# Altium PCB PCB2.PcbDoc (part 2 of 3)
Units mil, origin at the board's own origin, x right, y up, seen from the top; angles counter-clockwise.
Board outline 10275.59 x 4173.23 mil, 2 copper layers (Top Layer, Bottom Layer); 158 components, 159 nets, 776 pads, 338 vias.
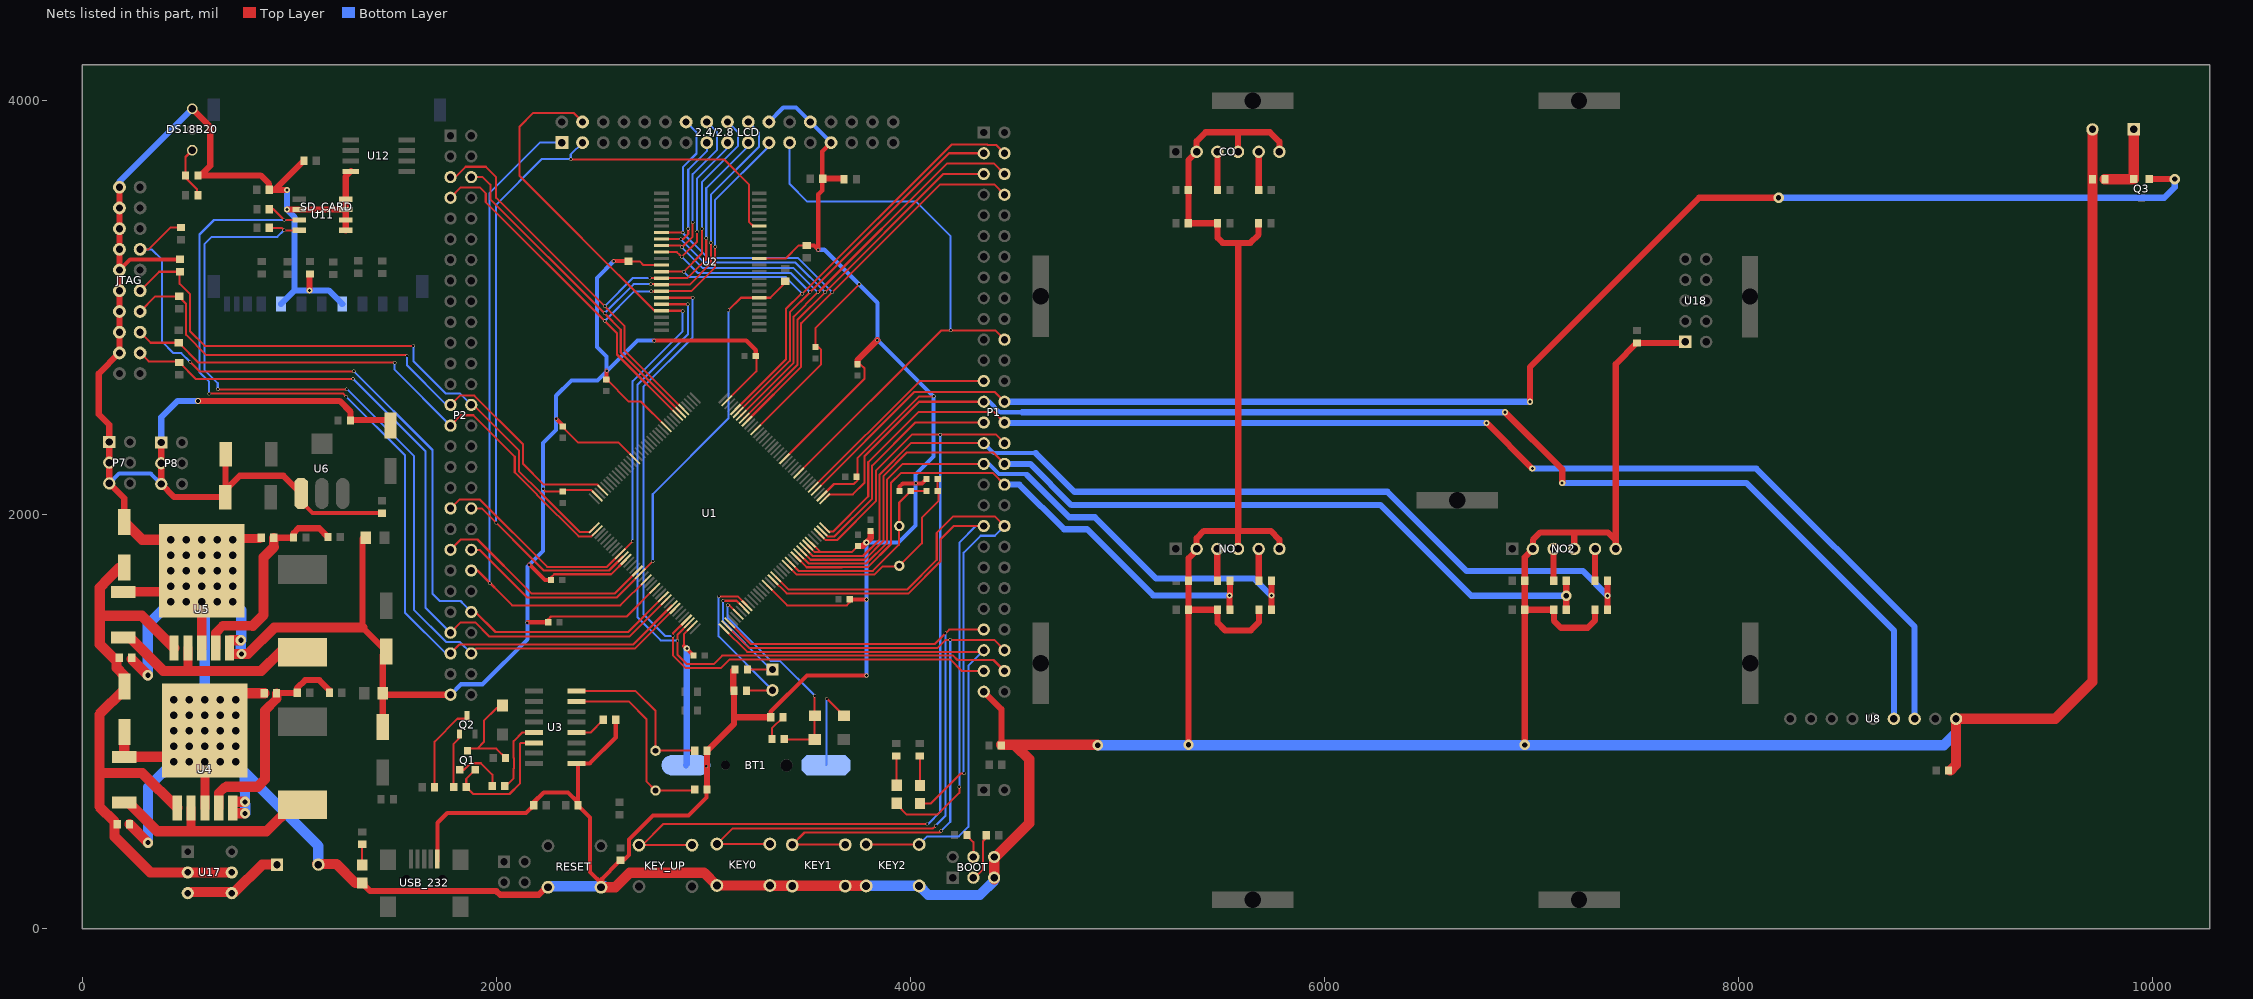
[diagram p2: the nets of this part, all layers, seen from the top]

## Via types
v1: diameter 16, hole 12, Top Layer to Bottom Layer, 183 vias
v2: diameter 60, hole 36, Top Layer to Bottom Layer, 50 vias
v3: diameter 27.56, hole 27.56, Top Layer to Bottom Layer, 32 vias
v4: diameter 30, hole 15, Top Layer to Bottom Layer, 27 vias
v5: diameter 50, hole 25, Top Layer to Bottom Layer, 19 vias
v6: diameter 125.98, hole 125.98, Top Layer to Bottom Layer, 16 vias
v7: diameter 20, hole 15, Top Layer to Bottom Layer, 4 vias
v8: diameter 196.85, hole 118.11, Top Layer to Bottom Layer, 4 vias
v9: diameter 30, hole 20, Top Layer to Bottom Layer, 1 vias
v10: diameter 40, hole 20, Top Layer to Bottom Layer, 1 vias
v11: diameter 50, hole 28, Top Layer to Bottom Layer, 1 vias

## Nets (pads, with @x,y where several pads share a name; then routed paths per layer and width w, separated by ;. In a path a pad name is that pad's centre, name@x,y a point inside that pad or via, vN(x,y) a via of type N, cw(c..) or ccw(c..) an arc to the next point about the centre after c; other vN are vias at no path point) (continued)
FSMC_D8: "2.4/2.8 LCD.14" P1.8 U1.64 U2.29 | length 3389.4
  Top Layer w10: U2.29@2797.28,3362.02 v1(2901.37,3362.02) ; U1.64@3210.96,2451.54 3472.37,2712.95 3472.37,2923.61 ; 3473.37,2923.61 v1(3622.37,3072.61) 4144.37,3594.61 4404.37,3594.61 P1.8@4454.37,3544.61
  Bottom Layer w10: v1@2898.87,3362.11 3021.37,3239.61 3455.37,3239.61 v1(3622.37,3072.61) ; v1(2901.37,3362.02) 2901.37,3677.67 2967,3743.3 2967,3846 2917,3896
FSMC_D9: "2.4/2.8 LCD.15" P1.5 U1.65 U2.30 | length 3194.6
  Top Layer w10: U2.30@2797.28,3330.53 v1(2890.45,3330.53) 2903.29,3330.53 2927.37,3354.61 v1(2927.37,3379.61) ; U1.65@3197.27,2465.19 3454.37,2722.28 3454.37,2939.61 v1(3588.37,3073.61) 4159.37,3644.61 P1.5@4354.37,3644.61
  Bottom Layer w10: v1@2891.37,3329.61 3004.37,3216.61 3445.37,3216.61 v1(3588.37,3073.61) ; v1(2927.37,3379.61) 2927.37,3665.37 3017,3755 3017,3796
FSMC_D10: "2.4/2.8 LCD.16" P1.6 U1.66 U2.31 | length 3472.9
  Top Layer w10: U2.31@2797.28,3299.03 2887.94,3299.03 v1(2896.37,3290.61) 2897.37,3290.61 2948.37,3341.61 v1(2948.37,3410.61) ; U1.66@3183.12,2479.37 3183.12,2479.81 3436.37,2733.06 3436.37,2955.61 v1(3553.37,3072.61) ; v1@3553.87,3072.11 4176.37,3694.61 4404.37,3694.61 P1.6@4454.37,3644.61
  Bottom Layer w10: v1(2896.37,3290.61) 2997.37,3189.61 3436.37,3189.61 v1(3553.37,3072.61) ; v1(2948.37,3410.61) 2948.37,3643.37 3067,3762 3067,3846 3017,3896
FSMC_D11: "2.4/2.8 LCD.17" P1.3 U1.67 U2.32 | length 3277.6
  Top Layer w10: U2.32@2797.28,3267.54 2872.44,3267.54 2885.37,3254.61 ; 2885.87,3254.11 v1(2895.99,3243.99) 2970.37,3318.37 v1(2970.37,3366.61) ; U1.67@3169.2,2493.29 3418.37,2742.46 3418.37,2976.61 v1(3515.37,3073.61) 4186.37,3744.61 P1.3@4354.37,3744.61
  Bottom Layer w10: v1(2895.99,3243.99) 2973.37,3166.61 3422.37,3166.61 v1(3515.37,3073.61) ; v1(2970.37,3366.61) 2970.37,3623.37 3126,3779 3126,3788
FSMC_D12: "2.4/2.8 LCD.18" P1.4 U1.68 U2.35 | length 3567.1
  Top Layer w10: U2.35@2797.28,3173.05 U2.35@2798.28,3173.05 v1(2905.81,3173.05) 2993.37,3260.61 v1(2993.37,3380.61) ; U1.68@3155.28,2507.21 3156.52,2507.21 3399.37,2750.06 3399.37,2993.06 3472.91,3066.61 v1(3478.37,3066.61) 4198.9,3787.13 4371.99,3787.13 4374.51,3784.61 4414.37,3784.61 P1.4@4454.37,3744.61
  Bottom Layer w10: v1(2905.81,3173.05) 2932.25,3146.61 3398.37,3146.61 v1(3478.37,3066.61) ; v1(2993.37,3380.61) 2993.37,3605.37 3168,3780 3168,3845 3117,3896
FSMC_D13: "2.4/2.8 LCD.19" P2.5 U1.77 U2.36 | length 2992.4
  Top Layer w10: P2.5@1779.37,3629.61 1802.37,3629.61 1852.37,3679.61 1949.37,3679.61 1999.37,3629.61 1999.37,3529.61 v1(2523.37,3005.61) 2620.37,2908.61 2620.37,2791.54 U1.77@2904.97,2506.95 ; v1(2742.37,3142.61) 2797.23,3142.61 U2.36@2798.28,3141.55 2923.32,3141.55 3014.37,3232.61 v1(3014.37,3334.61)
  Bottom Layer w10: v1(2523.37,3005.61) 2660.37,3142.61 v1(2742.37,3142.61) ; v1(3014.37,3334.61) 3014.37,3576.37 3217,3779 3217,3796
FSMC_D14: "2.4/2.8 LCD.20" P2.6 U1.78 U2.37 | length 3003.7
  Top Layer w10: P2.6@1879.37,3629.61 1934.37,3629.61 1971.37,3592.61 1971.37,3523.21 v1(2522.97,2971.61) 2601.37,2893.21 2601.37,2782.7 U1.78@2891.05,2493.03 ; v1(2746.37,3112.61) 2795.73,3112.61 U2.37@2798.28,3110.06 2933.82,3110.06 3036.37,3212.61 v1(3036.37,3312.61)
  Bottom Layer w10: v1(2522.97,2971.61) 2663.97,3112.61 v1(2746.37,3112.61) ; v1(3036.37,3312.61) 3036.37,3543.37 3268,3775 3268,3845 3217,3896
FSMC_D15: "2.4/2.8 LCD.21" P2.7 U1.79 U2.38 | length 3008.1
  Top Layer w10: P2.7@1779.37,3529.61 1829.37,3579.61 1920.37,3579.61 1949.37,3550.61 1949.37,3508.61 v1(2523.37,2934.61) 2583.37,2874.61 2583.37,2772.86 ; 2583.37,2772.61 2583.37,2772.86 ; v1(2748.37,3077.61) U2.38@2797.33,3077.61 ; U2.38@2798.28,3078.56 2941.32,3078.56 3057.37,3194.61 v1(3057.37,3292.61) ; U1.79@2877.13,2479.11 2583.37,2772.86
  Bottom Layer w10: v1(2523.37,2934.61) 2666.37,3077.61 v1(2748.37,3077.61) ; v1(3057.37,3292.61) 3057.37,3519.37 3317,3779 3317,3796
FSMC_NBL0: P1.53 U1.141 U2.39 | length 3728.1
  Top Layer w10: U2.39@2798.28,3047.06 v1(2948.83,3047.06) ; U1.141@2918.89,1490.83 2853.37,1425.31 v1(2853.37,1413.61) 2853.37,1319.61 2913.37,1259.61 3086.37,1259.61 3127.37,1300.61 4192.37,1300.61 4248.37,1244.61 P1.53@4354.37,1244.61
  Bottom Layer w10: v1(2853.37,1413.61) 2816.37,1413.61 2710.37,1519.61 2710.37,2616.61 2948.83,2855.06 v1(2948.83,3047.06)
FSMC_NBL1: P1.54 U1.142 U2.40 | length 3813.8
  Top Layer w10: U2.40@2798.28,3015.57 v1(2925.37,3015.61) v1(2925.37,3015.61) ; v1@2874.37,1387.61 2874.37,1418.48 U1.142@2932.8,1476.91 ; v1@2875.37,1398.61 v1(2875.37,1391.61) 2875.37,1323.61 2921.37,1277.61 3050.37,1277.61 3091.37,1318.61 4206.37,1318.61 4227.37,1297.61 4401.37,1297.61 P1.54@4454.37,1244.61
  Bottom Layer w10: v1(2875.37,1391.61) 2794.37,1391.61 2794.87,1392.11 2682.37,1504.61 2682.37,2626.61 2925.37,2869.61 v1(2925.37,3015.61)
FSMC_NE2: P2.41 U1.124 | length 1077.4
  Top Layer w10: P2.41@1779.37,1829.61 1829.37,1879.61 1909.37,1879.61 2169.43,1619.54 2573.84,1619.54 2682.02,1727.73 U1.124@2683.49,1727.73
FSMC_NE3: P2.42 R1.1 U1.125 U2.6 | length 2744.8
  Top Layer w10: P2.42@1879.37,1829.61 1919.37,1829.61 2149.37,1599.61 2581.74,1599.61 v1(2755.74,1773.61) ; v1(3121.37,2986.52) 3181.91,3047.06 U2.6@3270.72,3047.06 3323.83,3047.06 3395.37,3118.61 R1.1@3395.37,3126.61
  Bottom Layer w10: v1(2755.74,1773.61) 2755.74,2097.98 3121.37,2463.61 v1(3121.37,2986.52)
FSMC_NE4: "2.4/2.8 LCD.1" P2.44 U1.127 | length 3299.5
  Top Layer w10: P2.44@1879.37,1729.61 1909.37,1729.61 2077.37,1561.61 2599.42,1561.61 U1.127@2723.78,1685.97
  Bottom Layer w10: v1(1968.37,1668.61) 1968.37,3553.61 2210.76,3796 2317,3796
FSMC_NOE: "2.4/2.8 LCD.4" P2.37 U1.118 U2.41 | length 3936.4
  Top Layer w10: P2.37@1779.37,2029.61 1821.9,2072.13 1921.9,2072.13 2246.43,1747.61 2534.87,1747.61 v1(2658.37,1871.11) ; 2417,3896 2373,3940 2335.23,3940 2178.76,3940 2112.37,3873.61 2112.37,3636.61 2413.37,3335.61 2413.37,3335.06 2764.36,2984.07 U2.41@2798.28,2984.07 v1@2897.91,2984.07
  Bottom Layer w10: v1(2658.37,1871.11) 2658.37,2643.61 2900.37,2885.61 v1(2900.37,2981.61)
FSMC_NWE: "2.4/2.8 LCD.3" P2.38 U1.119 U2.17 | length 4127.2
  Top Layer w10: P2.38@1879.37,2029.61 1929.37,2029.61 2229.37,1729.61 2544.71,1729.61 U1.119@2612.42,1797.32 ; v1@2360,3714.61 3100.37,3714.61 3220.37,3594.61 3220.37,3413.68 3240.53,3393.52 U2.17@3270.72,3393.52
  Bottom Layer w10: v1(1999.37,1959.61) 1999.37,3496.61 2218.76,3716 v1(2360,3716) 2360,3739 2417,3796
GND: "2.4/2.8 LCD.22" "2.4/2.8 LCD.26" "2.4/2.8 LCD.27" BOOT.5 BOOT.6 BT1.2 C1.2 C2.2 C3.2 C4.2 C5.1 C6.1 C8.1 C9.1 C10.1 C11.1 C12.1 C13.1 C14.1 C15.1 C16.1 C17.1 C18.1 C19.1 C20.1 C21.1 C22.1 C23.1 C24.1 C25.2 C26.1 C27.1 C28.1 C29.1 C30.1 C31.2 C32.2 C33.2 C34.1 C35.2 C36.2 C37.2 C38.2 C39.2 C40.2 C41.2 C42.1 C43.2 C45.2 C46.1 C47.2 C49.2 C50.2 C51.2 C52.2 C53.1 C54.1 CO.2 CO.4 CO.6 D4.1 D5.1 D6.1 D7.1 DS18B20.1 JTAG.4 JTAG.6 JTAG.8 JTAG.10 JTAG.12 JTAG.14 JTAG.16 JTAG.18 JTAG.20 KEY0.1 KEY1.1 KEY2.1 NO2.2 NO2.4 NO2.6 NO.2 NO.4 NO.6 P1.55 P2.55 P7.1 P7.3 P7.5 P8.1 P8.3 P8.5 P9.2 POWER.2 R13.2 R14.2 R32.1 R33.1 R36.1 R37.1 R39.1 R41.1 R42.2 R44.2 R46.1 RESET.2 SD_CARD.3 SD_CARD.6 SYS.2 U1.16 U1.30 U1.31 U1.38 U1.51 U1.61 U1.71 U1.83 U1.94 U1.107 U1.120 U1.130 U1.143 U2.12 U2.34 U3.1 U4.3 U4.5 U5.3 U5.5 U6.1 U8.1 U11.1 U11.2 U11.3 U11.4 U11.6 U12.4 U18.1 USB_232.5 | length 54478
  Top Layer w10: v1(2226.37,2123.61) 2239.37,2110.61 C16.1@2321.37,2110.61 ; C14.1@2251.37,1479.61 2251.37,1494.61 2264.37,1507.61 2629.43,1507.61 U1.130@2765.77,1643.94 ; C15.1@2264.37,1683.61 2264.37,1696.61 2279.37,1711.61 2555.05,1711.61 U1.120@2626.58,1783.14 ; C17.1@2319.37,2423.61 2395.37,2347.61 2591.05,2347.61 U1.94@2668.34,2270.32 ; C16.1@2321.37,2109.61 2330.37,2118.61 2458.14,2118.61 U1.107@2487.38,2089.36 ; C18.1@2532.87,2653.11 2640.37,2545.61 2699.27,2545.61 U1.83@2821.45,2423.43 ; C1.2@2637.37,3222.61 C1.2@2638.37,3222.61 2693.24,3222.61 2711.31,3204.54 U2.34@2798.28,3204.54 ; 2906.37,1365.61 2906.37,1422.64 U1.143@2946.72,1462.99 ; v4(2920.37,1352.63) 2920.37,1350.61 v4@2921.37,1350.61 ; U1.71@3113.76,2548.7 3256.37,2691.32 C19.1@3256.37,2761.61 ; U1.61@3252.95,2409.51 3569.37,2725.93 3569.37,2795.61 3556.37,2808.61 C20.1@3541.37,2808.61 3541.37,2900.37 v1(3753,3112) ; U2.12@3270.72,3236.04 3396.8,3236.04 3460.37,3299.61 C2.2@3499.37,3299.61 ; U1.16@3308.63,1657.86 3404.89,1561.61 3693.37,1561.61 3707.37,1575.61 C23.1@3707.37,1590.61 ; U1.51@3392.15,2270.32 3778.37,2656.54 3778.37,2705.61 3757.37,2726.61 C21.1@3744.37,2726.61 ; U1.30@3503.27,1853 3536.66,1819.61 3564.47,1819.61 ; U1.31@3517.17,1866.9 U1.31@3517.42,1866.65 3564.47,1819.61 ; U1.38@3573.1,2089.36 3631.34,2147.61 3727.37,2147.61 3745.37,2165.61 3745.37,2274.06 4041.91,2570.61 v1(4112.37,2570.61) ; C23.1@3711.37,1591.61 C23.1@3712.37,1590.61 ; C24.1@3746.37,1847.61 3718.37,1819.61 3564.47,1819.61
  Top Layer w20: JTAG.12@180.37,3180.61 228.37,3228.61 ; 232.37,3231.61 R13.2@469.37,3231.61 ; R13.2@465.37,3228.61 R13.2@471.37,3234.61 ; U6.1@1058.4,2060.57 1112.37,2006.61 C51.2@1448.37,2006.61 ; USB_232.5@1716.37,326.74 1716.37,511.61 1763.37,558.61 2144.37,558.61 C29.1@2181.37,595.61 2181.37,610.61 2229.37,658.61 2347.37,658.61 C28.1@2395.37,610.61 ; v1@2151.37,1479.61 C14.1@2251.37,1479.61 ; v1(2160.37,1758.61) 2235.37,1683.61 C15.1@2264.37,1683.61 ; v1(2290.37,2461.61) 2319.37,2432.61 C17.1@2319.37,2423.61 ; U3.1@2387.73,797.61 2451.37,797.61 2577.37,923.61 C25.2@2577.37,1008.61 ; U3.1@2395.37,789.97 C28.1@2395.37,610.61 ; RESET.2@2512.28,200 2512.28,242.28 C12.1@2589.06,319.06 ; RESET.2@2512.28,214.61 2453.37,273.51 2453.37,537.61 C28.1@2395.37,595.61 C28.1@2395.37,610.61 ; C18.1@2533.37,2653.61 v1(2533.37,2694.61) ; v1(2567.37,3223.61) C1.2@2637.37,3223.61 ; C12.1@2597.37,334.61 2619.37,334.61 2640.37,355.61 2640.37,430.61 2756.37,546.61 2928.37,546.61 3015.37,633.61 C27.1@3015.37,668.61 ; v1(2763.37,2839.61) 3207.37,2839.61 3253.37,2793.61 C19.1@3253.37,2765.61 ; 2906.37,1365.61 v4@2920.87,1351.11 ; v4@2921.37,1350.61 C13.1@2952.37,1319.61 ; R14.2@3325.37,1021.61 3325.37,1047.61 3501.37,1223.61 v7(3787.37,1223.61) ; C2.2@3499.37,3299.61 3534.37,3299.61 v1(3555.37,3278.61) 3555.37,3546.61 3574.37,3565.61 3574.37,3753.37 3617,3796 ; C23.1@3712.37,1590.61 v7(3787.37,1590.61) ; C8.1@3947.37,2113.61 3947.37,2134.61 3963.37,2150.61 4056.37,2150.61 C9.1@4077.37,2171.61
  Top Layer w30: JTAG.20@193.37,3580.61 JTAG.20@180.37,3580.61 JTAG.18@180.37,3480.61 JTAG.14@180.37,3280.61 JTAG.12@180.37,3180.61 JTAG.10@180.37,3080.61 JTAG.8@180.37,2980.61 JTAG.4@180.37,2780.61 80.37,2680.61 80.37,2484.61 131.37,2433.61 P7.1@131.37,2350.61 P7.3@131.37,2250.61 P7.5@131.37,2150.61 203.37,2078.61 C45.2@203.37,1964.84 ; P8.1@382.37,2347.61 P8.3@382.37,2247.61 P8.5@382.37,2147.61 445.37,2084.61 D6.1@691.37,2084.61 691.37,2117.61 D6.1@693.37,2119.61 ; U5.3@400.37,1626.61 v2(427.37,1653.61) ; DS18B20.1@532.37,3959.61 619.37,3872.61 619.37,3684.61 C31.2@572.37,3637.61 ; v9(560.37,2548.61) 1243.37,2548.61 1296.37,2495.61 C49.2@1296.37,2454.61 ; C31.2@569.37,3637.61 C31.2@572.37,3637.61 ; v2(592.37,806.61) U4.3@593.37,805.61 ; D6.1@693.37,2086.61 D6.1@693.37,2119.61 ; D7.1@693.37,2291.61 D6.1@693.37,2119.61 ; v2(742.37,1106.61) U4.3@773.37,1137.61 ; v4(989.37,3473.61) U11.6@1047.96,3473.61 ; v4(989.37,3566.61) 905.37,3566.61 C32.2@903.37,3568.61 ; U11.6@1048.96,3473.61 U11.3@1273.37,3473.61 ; U6.1@1058.4,2060.57 U6.1@1058.4,2101.54 972.34,2187.61 761.37,2187.61 D6.1@693.37,2119.61 ; C33.2@1071.37,3708.61 931.37,3568.61 C32.2@903.37,3568.61 ; v4(1098.37,3082.61) C30.1@1098.37,3159.61 ; U11.1@1273.37,3372.61 U11.2@1273.37,3422.61 U11.3@1273.37,3473.61 ; C49.2@1296.37,2456.61 C50.2@1485.61,2456.61 ; U12.4@1298.37,3657.54 1273.37,3632.54 U11.4@1273.37,3522.61 U11.3@1273.37,3473.61 ; SYS.2@1352.31,220.57 1391.13,181.74 2001.24,181.74 2019.37,163.61 2205.37,163.61 RESET.2@2256.37,214.61 ; C54.1@1354.37,1883.61 1354.37,1454.37 C47.2@1469.37,1339.37 ; C43.2@1452.37,974.84 C53.1@1452.37,1136.61 ; C47.2@1452.37,1322.37 C53.1@1452.37,1136.61 ; P2.55@1779.37,1129.61 1459.37,1129.61 C53.1@1452.37,1136.61 ; C18.1@2531.37,2651.61 2532.87,2653.11 C18.1@2533.37,2653.61 ; C27.1@3018.37,672.61 C26.1@3018.37,859.61 3148.37,989.61 3148.37,1020.61 ; C6.1@3144.37,1150.61 C5.1@3144.37,1248.61 ; C6.1@3148.37,1149.61 3148.37,1020.61 ; R14.2@3325.37,1021.61 3149.37,1021.61 3148.37,1020.61 ; C3.2@3574.37,3622.61 3676.37,3622.61 C4.2@3679.37,3619.61 ; C21.1@3744.37,2725.61 3744.37,2726.61 3744.37,2745.61 v1(3840.37,2841.61) ; C24.1@3746.37,1847.61 3770.37,1847.61 v4(3787.37,1864.61) 3809,1886.24 C11.1@3809,1913.98 ; P1.55@4354.37,1144.61 4439.37,1059.61 C10.1@4439.37,888.61 ; v5@5343.37,879.06 C37.2@5343.37,1540.74 ; 5581.02,1920.74 5417.37,1920.74 5382.2,1885.57 5382.2,1827.84 5343.37,1789.02 C38.2@5343.37,1680.74 C37.2@5343.37,1540.74 ; NO.4@5582.2,1827.84 NO.4@5582.2,1833.84 5582.2,1919.57 5583.37,1920.74 ; CO.4@5582.2,3751.84 5582.2,3845.74 ; R32.1@5681.37,3406.74 5681.37,3351.74 5641.37,3311.74 5582.91,3311.74 ; R37.1@5683.37,1540.74 5683.37,1480.74 5643.37,1440.74 5519.37,1440.74 5483.37,1476.74 R36.1@5483.37,1540.74 C37.2@5343.37,1540.74 ; NO.6@5782.2,1827.84 5782.2,1878.91 5740.37,1920.74 5583.37,1920.74 ; CO.6@5782.2,3751.84 5782.2,3799.91 5736.37,3845.74 5582.2,3845.74 ; v5@6966.37,880.06 C40.2@6966.37,1540.74 ; NO2.4@7206.17,1833.84 7206.17,1913.54 ; R41.1@7306.37,1540.74 7306.37,1488.74 7271.37,1453.74 7141.37,1453.74 7107.37,1487.74 R39.1@7107.37,1540.74 C40.2@6966.37,1540.74 ; NO2.6@7406.17,1833.84 7406.17,1874.94 ; U18.1@7738.06,2828.74 C34.1@7508.37,2828.74 7406.17,2726.54 7406.17,1874.94 ; C31.2@572.37,3637.61 862.37,3637.61 903.37,3596.61 C32.2@903.37,3568.61 ; 5582.2,3845.74 5425.37,3845.74 5382.2,3802.57 CO.2@5382.2,3751.84 5342.37,3712.02 C35.2@5342.37,3566.74 C36.2@5342.37,3406.74 R33.1@5483.37,3406.74 5483.37,3335.74 5507.37,3311.74 5582.91,3311.74 ; 5582.91,3311.74 5583.37,3311.28 5583.37,1920.74 ; C40.2@6966.37,1540.74 C39.2@6966.37,1680.74 6966.37,1794.05 NO2.2@7006.17,1833.84 7006.17,1877.54 7042.37,1913.74 7042.57,1913.54 7206.17,1913.54 ; 7206.17,1913.54 7367.57,1913.54 7406.17,1874.94
  Top Layer w45: D4.1@199.37,1626.61 U5.3@400.37,1626.61 ; U5.3@578.37,1355.26 U5.3@578.37,1577.61 ; U4.3@593.37,583.26 U4.3@593.37,805.61 ; U5.3@728.37,1884.61 R42.2@857.37,1884.61
  Top Layer w50: C45.2@203.37,1964.84 289.61,1878.61 v2(427.37,1878.61) ; C41.2@204.37,949.37 D5.1@204.37,829.61 U4.3@419.37,829.61 ; C42.1@229.37,504.61 v5(318.37,415.61) ; C46.1@239.37,1302.15 v5(317.91,1223.61) ; U5.5@714.91,1326.61 v5(769.91,1326.61) 800.91,1326.61 928.68,1454.37 1354.37,1454.37 ; U5.5@718.91,1392.61 v5(766.91,1392.61) ; 753.83,556.8 v5(786.72,556.8) ; 756.37,612.26 v5(786.72,612.26) ; U4.3@773.37,1137.61 R44.2@879.37,1137.61 ; POWER.2@1135.37,312.74 1228.24,312.74 1320.41,220.57 SYS.2@1352.31,220.57 ; RESET.2@2512.28,200 2574.63,200 2645.24,270.61 3003.46,270.61 KEY0.1@3065.46,208.61 KEY0.1@3321.37,208.61 ; KEY0.1@3321.37,206.61 KEY2.1@3786.46,206.61 ; BOOT.5@4404.37,239.61 4404.37,339.61 4574.37,509.61 4574.37,817.74 4507.5,884.61 ; C10.1@4439.37,888.61 v5@4903.24,888.61 ; C52.2@9021.37,763.74 9049.37,791.74 U8.1@9049.37,1013.74 9529.05,1013.74 9707.37,1192.06 ; 9708.37,1193.06 P9.2@9708.37,3861.61
  Bottom Layer w20: P7.5@131.37,2150.61 179.37,2198.61 331.37,2198.61 P8.5@382.37,2147.61 ; P2.55@1779.37,1129.61 1830.37,1180.61 1933.37,1180.61 2150.37,1397.61 v1(2150.37,1478.61) 2150.37,1748.61 v1(2160.37,1758.61) 2226.37,1824.61 2226.37,2345.61 2289.37,2408.61 2289.37,2460.61 v1(2290.37,2461.61) ; v1@2289.37,2461.61 2289.37,2573.61 2363.37,2647.61 2489.37,2647.61 v1@2533.37,2691.61 ; v1(2533.37,2694.61) 2533.37,2762.61 2486.37,2809.61 2486.37,3142.61 v1(2567.37,3223.61) ; v1@2536.37,2694.61 2681.37,2839.61 v1(2763.37,2839.61) ; 3317,3896 3386,3965 3448,3965 3517,3896 3617,3796 ; v1(3555.37,3278.61) 3584.37,3278.61 3840.37,3022.61 3840.37,2842.61 v1(4112.37,2570.61) ; v7(3787.37,1223.61) v7(3787.37,1590.61) v4(3787.37,1864.61) 3942.37,1864.61 4025.37,1947.61 v1(4025.37,2151.61) 4025.37,2193.61 4112.37,2280.61 v1@4112.37,2568.61
  Bottom Layer w30: JTAG.20@180.37,3580.61 180.37,3607.61 DS18B20.1@532.37,3959.61 ; P8.1@382.37,2347.61 382.37,2469.61 461.37,2548.61 v9(560.37,2548.61) ; v2(727.37,1578.61) 768.91,1537.06 ; v2@742.37,798.61 784.72,756.26 ; SD_CARD.6@960.91,3016.97 1026.55,3082.61 ; v4(989.37,3566.61) v4(989.37,3473.61) 1026.55,3436.43 1026.55,3082.61 ; SD_CARD.3@1256.19,3016.97 1190.55,3082.61 v4(1098.37,3082.61) 1026.55,3082.61 ; BT1.2@2915.85,789.61 2920.37,794.12 v4(2920.37,1352.63) ; v1(3840.37,2841.61) v1@3840.37,2842.61 ; BOOT.5@4404.37,232.61 BOOT.5@4404.37,239.61
  Bottom Layer w50: v5@316.91,1223.61 316.91,1468.15 v2(427.37,1578.61) ; v5(318.37,415.61) 318.37,682.61 v2(442.37,806.61) ; v2(592.37,1106.61) v2@592.37,1563.61 ; v5@766.91,1329.61 v5(766.91,1392.61) ; v5@768.91,1392.61 768.91,1537.06 ; v5@787.49,556.81 784.72,756.26 1141.37,399.61 POWER.2@1141.37,309.74 ; RESET.2@2266.37,204.61 RESET.2@2522.28,204.61 ; KEY2.1@3786.46,206.61 KEY2.1@4042.37,206.61 4086.24,162.74 4334.5,162.74 BOOT.5@4404.37,232.61 ; v5@4908.64,886.74 8990.37,886.74 9049.37,945.74 U8.1@9049.37,1013.74
  other v1: 3015.37,783.61
  other v2: 517.37,806.61 667.37,806.61 742.37,806.61 442.37,881.61 517.37,881.61 592.37,881.61 667.37,881.61 742.37,881.61 442.37,956.61 517.37,956.61 592.37,956.61 667.37,956.61 742.37,956.61 442.37,1031.61 517.37,1031.61 592.37,1031.61 667.37,1031.61 742.37,1031.61 442.37,1106.61 517.37,1106.61 667.37,1106.61 502.37,1578.61 577.37,1578.61 652.37,1578.61 502.37,1653.61 577.37,1653.61 652.37,1653.61 727.37,1653.61 427.37,1728.61 502.37,1728.61 577.37,1728.61 652.37,1728.61 727.37,1728.61 427.37,1803.61 502.37,1803.61 577.37,1803.61 652.37,1803.61 727.37,1803.61 502.37,1878.61 577.37,1878.61 652.37,1878.61 727.37,1878.61
  other v5: 4904.37,885.74 6966.37,887.61 5343.37,888.61
IIC_SCL: P2.51 R28.2 U1.136 U11.7 | length 4688.2
  Top Layer w10: v1(613.37,2583.61) 1261.37,2583.61 v1(1275.37,2569.61) ; R28.2@904.37,3474.61 924.37,3474.61 v1(976.37,3422.61) U11.7@1048.96,3422.61 ; P2.51@1779.37,1329.61 1822.37,1372.61 2660.97,1372.61 U1.136@2849.05,1560.69
  Bottom Layer w10: v1(613.37,2583.61) 613.37,2641.61 567.37,2687.61 567.37,3352.61 637.37,3422.61 v1(976.37,3422.61) ; v1(1275.37,2569.61) 1559.37,2285.61 1559.37,1525.61 1755.37,1329.61 P2.51@1779.37,1329.61
IIC_SDA: P2.52 R29.2 U1.137 U11.8 | length 4554.4
  Top Layer w10: v1(655.37,2604.61) v1(1277.37,2604.61) ; R29.2@900.25,3384.61 R29.2@904.37,3384.61 963.37,3384.61 v1(975.37,3372.61) U11.8@1048.96,3372.61 ; P2.52@1879.37,1329.61 1902.37,1352.61 2668.81,1352.61 U1.137@2862.97,1546.77
  Bottom Layer w10: v1(655.37,2604.61) 655.37,2634.61 590.37,2699.61 590.37,3304.61 626.37,3340.61 943.37,3340.61 v1(975.37,3372.61) ; v1(1277.37,2604.61) 1280.81,2604.61 1602.37,2283.05 1602.37,1540.61 1758.37,1384.61 1824.37,1384.61 P2.52@1879.37,1329.61
JTCK: JTAG.9 P2.28 R13.1 U1.109 | length 3001.5
  Top Layer w10: JTAG.9@280.37,3080.61 372.37,3172.61 471.37,3172.61 471.37,3114.61 520.37,3065.61 520.37,2886.61 592.37,2814.61 v1(1600.37,2814.61) ; P2.28@1879.37,2529.61 1889.37,2529.61 2109.37,2309.61 2109.37,2209.61 2214.37,2104.61 2214.37,2103.91 2402.67,1915.61 2452.32,1915.61 U1.109@2473.23,1936.52
  Bottom Layer w10: v1(1600.37,2814.61) 1600.37,2740.61 1757.37,2583.61 1825.37,2583.61 P2.28@1879.37,2529.61
JTDI: JTAG.5 P2.29 R6.2 U1.110 | length 2732.2
  Top Layer w10: JTAG.5@280.37,2880.61 331.37,2829.61 R6.2@466.37,2829.61 562.37,2733.61 1508.37,2733.61 v1(1509.37,2732.61) ; P2.29@1779.37,2429.61 1829.37,2479.61 1889.51,2479.61 2089.37,2279.75 2089.37,2204.15 2196.37,2097.15 2196.37,2096.45 2398.16,1894.66 2459.21,1894.66 U1.110@2487.15,1922.6
  Bottom Layer w10: v1(1509.37,2732.61) 1509.37,2699.61 P2.29@1779.37,2429.61
JTDO: JTAG.13 P2.48 R10.2 U1.133 | length 4243.3
  Top Layer w10: JTAG.13@280.37,3280.61 321.37,3280.61 427.37,3386.61 R10.2@473.25,3386.61 ; R10.2@477.37,3382.49 R10.2@477.37,3386.61 ; v1(521.37,2737.61) 567.37,2691.61 v1(1312.37,2691.61) ; P2.48@1879.37,1529.61 1899.37,1529.61 1996.37,1432.61 2637.45,1432.61 U1.133@2807.3,1602.45
  Bottom Layer w10: JTAG.13@280.37,3280.61 335.37,3280.61 386.37,3229.61 386.37,2834.61 441.37,2779.61 479.37,2779.61 v1(521.37,2737.61) ; v1(1312.37,2691.61) 1692.37,2311.61 1692.37,1617.61 1728.37,1581.61 1830.37,1581.61 1833.37,1578.61 1833.37,1575.61 P2.48@1879.37,1529.61
JTMS: JTAG.7 P2.27 R7.2 U1.105 | length 2829.3
  Top Layer w10: JTAG.7@280.37,2980.61 353.37,3053.61 R7.2@469.37,3053.61 469.37,3049.49 502.37,3016.49 502.37,2867.61 600.37,2769.61 v1@1567.37,2769.61 ; P2.27@1779.37,2529.61 1824.37,2574.61 1894.51,2574.61 2129.37,2339.75 2129.37,2245.61 2230.37,2144.61 2474.13,2144.61 2474.4,2144.87 2487.59,2144.87 U1.105@2514.99,2117.47
  Bottom Layer w10: v1(1569.37,2767.61) 1569.37,2720.61 P2.27@1752.37,2537.61
JTRST: JTAG.3 P2.49 R5.2 U1.134 | length 3666.1
  Top Layer w10: JTAG.3@280.37,2780.61 321.37,2739.61 464.37,2739.61 R5.2@469.37,2734.61 549.37,2654.61 v1@1308.37,2654.61 ; P2.49@1779.37,1429.61 1829.37,1479.61 1898.37,1479.61 1967.37,1410.61 2643.29,1410.61 U1.134@2821.22,1588.53
  Bottom Layer w10: v1(1308.37,2655.61) 1658.37,2305.61 1658.37,1550.61 P2.49@1779.37,1429.61
KEY0: KEY0.2 P1.49 U1.3 | length 3609.4
  Top Layer w10: KEY0.2@3055.46,384.61 KEY0.2@3055.46,398.61 ; U1.3@3127.44,1477.18 3230.01,1374.61 4117.37,1374.61 v1@4169.37,1426.61 ; KEY0.2@3321.37,408.61 KEY0.2@3065.46,408.61 3141.46,484.61 4109.37,484.61 v1@4120.37,495.61 ; v1@4169.87,1427.11 4187.37,1444.61 P1.49@4354.37,1444.61
  Bottom Layer w10: v1(4121.37,496.61) 4169.37,544.61 v1(4169.37,1427.61)
KEY1: KEY1.2 P1.52 U1.2 | length 3365.9
  Top Layer w10: U1.2@3113.52,1463.26 3222.18,1354.61 4130.28,1354.61 4170.28,1394.61 v1@4191.37,1394.61 ; KEY1.2@3685.37,405.61 KEY1.2@3429.46,405.61 3488.46,464.61 4140.37,464.61 v1(4149.37,473.61) ; v1@4192.37,1394.61 4404.37,1394.61 P1.52@4454.37,1344.61
  Bottom Layer w10: v1(4149.37,473.61) 4192.37,516.61 v1(4192.37,1395.61)
KEY2: KEY2.2 P1.51 U1.1 | length 2742.2
  Top Layer w10: U1.1@3099.6,1449.34 3212.34,1336.61 4213.83,1336.61 4214.83,1335.61 4345.37,1335.61 P1.51@4354.37,1344.61 ; KEY2.2@3786.46,406.61 KEY2.2@4042.37,406.61
  Bottom Layer w10: KEY2.2@4040.37,383.61 4040.37,404.61 KEY2.2@4042.37,406.61 4081.37,445.61 4234.37,445.61 4280.37,491.61 4280.37,1270.61 P1.51@4354.37,1344.61
LCD_BL: "2.4/2.8 LCD.23" P1.22 U1.46 | length 2833.3
  Top Layer w10: U1.46@3461.51,2200.99 4150.13,2889.61 v1(4194.37,2889.61) 4409.37,2889.61 P1.22@4454.37,2844.61
  Bottom Layer w10: 3417,3796 3417,3595.98 3500.37,3512.61 4026.37,3512.61 4194.37,3344.61 v1(4194.37,2889.61)
LED0: DS0.2 P1.39 U1.18 | length 2959.8
  Top Layer w10: U1.18@3336.23,1685.97 3402.6,1619.61 3721.42,1619.61 3721.49,1619.67 3762.25,1619.67 3762.32,1619.61 3991.19,1619.61 4145.37,1773.78 4145.37,1880.61 4209.37,1944.61 P1.39@4354.37,1944.61 ; DS0.2@3940.31,593.67 3983.37,550.61 4130.37,550.61 4236.37,656.61 v1(4236.37,684.61)
  Bottom Layer w10: v1(4236.37,684.61) 4236.37,1864.61 4316.37,1944.61 P1.39@4354.37,1944.61
LED1: DS1.2 P1.40 U1.19 | length 2958.5
  Top Layer w10: U1.19@3350.15,1699.89 3412.43,1637.61 3713.97,1637.61 3714.03,1637.67 3769.71,1637.67 3769.77,1637.61 3983.74,1637.61 4127.37,1781.24 4127.37,1911.61 4205.37,1989.61 4409.37,1989.61 P1.40@4454.37,1944.61 ; DS1.2@4046.31,604.57 4098.33,604.57 4243.37,749.61 v1(4259.37,749.61)
  Bottom Layer w10: v1@4257.37,751.61 4257.37,1815.61 4339.37,1897.61 4407.37,1897.61 P1.40@4454.37,1944.61
NetBOOT_3: BOOT.3 R11.1 | length 234.6
  Top Layer w10: BOOT.3@4304.37,239.61 4351.37,286.61 4351.37,423.61 R11.1@4373.37,445.61
NetBOOT_4: BOOT.4 R12.2 | length 121.8
  Top Layer w10: R12.2@4273.37,448.61 4304.37,417.61 BOOT.4@4304.37,339.61
NetBT1_1: BT1.1 D1.1 | length 441.8
  Top Layer w10: v1(3595.37,1111.61) D1.1@3679.37,1027.61
  Bottom Layer w10: BT1.1@3593.02,789.61 3595.37,791.96 v1(3595.37,1111.61)
NetC5_2: C5.2 U1.8 Y1.1 | length 678.4
  Top Layer w10: v1@3094.37,1583.61 3160.21,1583.61 U1.8@3197.04,1546.77 ; C5.2@3213.37,1251.61 Y1.1@3334.37,1251.61
  Bottom Layer w10: v1(3095.37,1583.61) 3095.37,1483.61 3311.37,1267.61 Y1.1@3311.37,1233.61
NetC6_2: C6.2 U1.9 Y1.2 | length 842.3
  Top Layer w10: v1(3074.37,1604.61) 3167.05,1604.61 U1.9@3210.96,1560.69 ; C6.2@3208.37,1149.61 3332.37,1149.61 Y1.2@3334.37,1151.61
  Bottom Layer w10: v1(3074.37,1604.61) 3074.37,1411.61 Y1.2@3334.37,1151.61
NetC7_1: C7.1 R14.1 | length 128.4
  Top Layer w10: C7.1@3331.37,915.61 3331.37,967.61 R14.1@3385.37,1021.61
NetC7_2: C7.2 D1.2 D2.2 U1.6 | length 1065.7
  Top Layer w10: v1(3117.37,1562.61) 3125.5,1562.61 U1.6@3169.43,1518.67 ; C7.2@3391.37,915.61 3393.37,913.61 D2.2@3538.37,913.61 ; D2.2@3537.37,914.61 v1(3537.37,1125.61)
  Bottom Layer w10: v1(3117.37,1562.61) 3117.37,1501.61 3324.84,1294.13 3369.28,1294.13 v1@3537.37,1126.05
NetC8_2: C8.2 R2.1 U1.24 Y2.1 | length 952.4
  Top Layer w10: U1.24@3419.75,1769.49 3461.63,1727.61 3676.69,1727.61 3676.75,1727.67 3818.43,1727.67 3944.37,1853.61 3944.37,1934.61 Y2.1@3937.37,1941.61 ; Y2.1@3946.37,1944.61 3946.37,2058.04 C8.2@4001.87,2113.54 ; C8.2@4001.93,2113.61 R2.1@4077.37,2113.61
NetC9_2: C9.2 R2.2 U1.23 Y2.2 | length 1054
  Top Layer w10: U1.23@3405.83,1755.57 3451.79,1709.61 3684.14,1709.61 3684.21,1709.67 3799.53,1709.67 3799.6,1709.61 3825.83,1709.61 3865.7,1749.48 Y2.2@3937.37,1749.48 ; Y2.2@3946.37,1752.48 4055.37,1861.48 4055.37,1984.61 4135.37,2064.61 R2.2@4135.37,2103.04 ; R2.2@4131.87,2113.54 C9.2@4131.87,2171.54
NetC25_1: C25.1 U3.4 | length 154.9
  Top Layer w10: U3.4@2387.73,947.61 2456.37,947.61 C25.1@2517.37,1008.61
NetC26_2: C26.2 U3.8 Y3.1 | length 802.4
  Top Layer w10: U3.8@2387.73,1147.61 2673.37,1147.61 2769.37,1051.61 Y3.1@2769.37,859.61 C26.2@2958.37,859.61
NetC27_2: C27.2 U3.7 Y3.2 | length 922.7
  Top Layer w10: U3.7@2387.73,1097.61 2640.37,1097.61 2725.37,1012.61 2725.37,711.48 Y3.2@2769.37,667.48 2954.24,667.48 C27.2@2955.37,668.61
NetC31_1: C31.1 DS18B20.3 R27.2 | length 261.9
  Top Layer w10: DS18B20.3@532.37,3759.61 499.37,3726.61 C31.1@499.37,3637.61 499.37,3625.61 555.37,3569.61 R27.2@555.37,3534.61
NetC41_1: C41.1 C42.2 C45.1 C46.2 U4.1 U5.1 U17.2 U17.5 | length 2982.2
  Top Layer w50: 86.91,1510.61 289.02,1510.61 U5.1@444.37,1355.26 ; C45.1@203.37,1744.61 182.37,1744.61 126.9,1689.13 126.65,1689.13 84.91,1647.4 84.91,1374.06 166.41,1292.56 166.41,1259.11 204.37,1221.15 C41.1@204.37,1169.61 ; C41.1@204.37,1155.06 83.91,1034.61 83.91,751.61 ; U4.1@459.37,583.26 291.02,751.61 83.91,751.61 ; U17.2@510.37,271.61 U17.5@723.97,271.61 ; U17.2@510.37,271.74 329.78,271.74 156.91,444.61 156.91,517.06 83.91,590.06 83.91,751.61
NetC44_2: C44.2 R44.1 R45.1 U4.4 | length 1079.9
  Top Layer w10: R45.1@1037.37,1137.61 R45.1@1039.37,1139.61
  Top Layer w30: R44.1@939.37,1137.61 R45.1@1037.37,1137.61 ; R45.1@1039.37,1139.61 1039.37,1162.61 1077.37,1200.61 1146.37,1200.61 1194.37,1152.61 C44.2@1194.37,1139.61
  Top Layer w45: U4.4@660.37,583.26 660.37,655.06 689.91,684.61 ; 883.37,1054.06 940.37,1111.06 R44.1@940.37,1137.61
  Top Layer w50: 699.37,685.61 847.91,685.61 883.37,721.06 883.37,1054.06
NetC48_2: C48.2 R42.1 R43.1 U5.4 | length 1042.6
  Top Layer w10: R43.1@1021.37,1889.61 1021.37,1910.61
  Top Layer w30: R42.1@925.37,1887.61 R43.1@1021.37,1887.61 ; 1021.37,1910.61 1044.37,1933.61 1145.37,1933.61 C48.2@1187.37,1891.61
  Top Layer w45: U5.4@645.37,1355.26 645.37,1428.06 679.91,1462.61 823.91,1462.61 ; 925.37,1843.06 R42.1@925.37,1887.61
  Top Layer w50: 823.91,1462.61 876.37,1515.06 876.37,1794.06 925.37,1843.06
NetCO_3: CO.3 R30.2 | length 183.9
  Top Layer w30: R30.2@5483.37,3566.74 CO.3@5483.37,3750.67
NetCO_5: CO.5 R31.2 | length 184.9
  Top Layer w30: R31.2@5682.37,3566.74 CO.5@5682.37,3751.67
NetD3_2: D3.2 Q1.3 R19.2 | length 472.3
  Top Layer w10: Q1.3@1861.37,859.87 1871.11,869.61 1908.11,869.61 ; D3.2@2033.37,1064.61 2001.37,1064.61 1940.37,1003.61 1940.37,901.87 1908.11,869.61 ; R19.2@2045.37,824.61 2000.37,869.61 1908.11,869.61
NetD4_2: D4.2 L1.1 U5.2 | length 1080.5
  Top Layer w10: 511.37,1245.61 512.37,1244.61
  Top Layer w30: D4.2@199.37,1406.61 D4.2@230.37,1406.61
  Top Layer w45: 511.37,1245.61 U5.2@511.37,1355.26
  Top Layer w50: D4.2@230.37,1406.61 392.37,1244.61 512.37,1244.61 865.91,1244.61 955.91,1334.61 L1.1@1064.37,1334.61
NetD5_2: D5.2 L2.1 U4.2 | length 1084.5
  Top Layer w10: D5.2@204.37,609.61 D5.2@223.37,609.61 ; 524.37,470.61 526.37,472.61
  Top Layer w45: 526.37,472.61 U4.2@526.37,583.26
  Top Layer w50: D5.2@223.37,609.61 362.37,470.61 524.37,470.61 890.61,470.61 1019.61,599.61 L2.1@1064.37,599.61
NetDS0_1: DS0.1 R24.2 | length 140.1
  Top Layer w10: DS0.1@3933.31,693.57 R24.2@3933.31,833.67
NetDS1_1: DS1.1 R25.2 | length 142.1
  Top Layer w10: DS1.1@4046.31,691.57 R25.2@4046.31,833.67
NetIN_1: POWER.1 U17.3 U17.4 | length 482.7
  Top Layer w50: U17.3@513.37,177.61 738.37,177.61 870.5,309.74 POWER.1@941.37,309.74
NetNO2_3: NO2.3 R38.2 | length 151.9
  Top Layer w30: R38.2@7106.17,1681.94 NO2.3@7106.17,1833.84
NetNO2_5: NO2.5 R40.2 | length 152.9
  Top Layer w30: R40.2@7306.37,1680.74 NO2.5@7306.37,1833.64
NetNO_3: NO.3 R34.2 | length 153.6
  Top Layer w30: NO.3@5482.2,1833.84 5482.2,1681.91 R34.2@5483.37,1680.74
NetNO_5: NO.5 R35.2 | length 151.9
  Top Layer w30: R35.2@5682.2,1681.91 NO.5@5682.2,1833.84
NetP9_1: P9.1 Q3.2 R46.2 | length 379.2
  Top Layer w30: Q3.2@9907.71,3619.61 Q3.2@9907.97,3619.87
  Top Layer w50: R46.2@9768.37,3619.61 Q3.2@9907.71,3619.61 ; Q3.2@9907.97,3619.87 P9.1@9907.97,3859.34
NetQ1_1: Q1.1 R15.1 | length 253.4
  Top Layer w10: Q1.1@1823.97,767.35 1837.11,767.35 1837.37,767.61 1844.23,767.61 1875.67,799.05 1925.81,799.05 1981.37,743.49 R15.1@1981.37,683.61
NetQ1_2: Q1.2 R16.2 U3.14 | length 657.2
  Top Layer w10: Q1.2@1898.77,767.35 1855.37,723.94 R16.2@1855.37,684.61 1889.37,650.61 2064.37,650.61 2114.37,700.61 2114.37,892.61 2119.37,897.61 U3.14@2183.01,897.61
NetQ2_1: Q2.1 R16.1 | length 255.6
  Top Layer w10: R16.1@1795.37,684.61 1793.25,686.72 1793.25,891.6 Q2.1@1826.97,925.31
NetQ2_3: Q2.3 R17.1 | length 427.7
  Top Layer w10: R17.1@1702.37,683.61 1702.37,903.61 1812.66,1013.9 Q2.3@1864.37,1013.9
NetR15_2: R15.2 U3.13 | length 356.3
  Top Layer w10: R15.2@2041.37,683.61 2084.37,726.61 2084.37,773.72 2084.87,774.22 2084.87,824.99 2084.37,825.49 2084.37,905.61 2126.37,947.61 U3.13@2183.01,947.61
NetR26_2: R26.2 SYS.1 | length 100
  Top Layer w10: SYS.1@1352.37,307.64 R26.2@1352.37,407.61
NO2_1: P1.34 R38.1 R39.2 U1.28 | length 4534.7
  Top Layer w10: U1.28@3475.43,1825.16 3518.98,1781.61 3654.32,1781.61 3654.38,1781.67 3778.89,1781.67 3869.37,1872.15 3869.37,2185.61 3983.37,2299.61 4399.37,2299.61 P1.34@4454.37,2244.61
  Top Layer w30: R39.2@7167.37,1540.74 v11(7167.37,1607.74) R38.1@7167.37,1680.74
  Bottom Layer w30: P1.34@4454.37,2244.61 4578.5,2244.61 4777.37,2045.74 6270.37,2045.74 6708.37,1607.74 v11(7167.37,1607.74)
NO2_2: P1.31 R40.1 R41.2 U1.29 | length 4748.3
  Top Layer w10: U1.29@3489.35,1839.08 3528.82,1799.61 3646.86,1799.61 3646.93,1799.67 3771.43,1799.67 3851.37,1879.61 3851.37,2193.61 4002.37,2344.61 P1.31@4354.37,2344.61
  Top Layer w30: R41.2@7366.37,1540.74 v4(7366.37,1607.74) R40.1@7366.37,1680.74
  Bottom Layer w20: P1.31@4354.37,2344.61 4402.24,2296.74 4605.37,2296.74
  Bottom Layer w30: 4605.37,2296.74 4792.37,2109.74 6303.37,2109.74 6685.37,1727.74 7246.37,1727.74 v4(7366.37,1607.74)
NO_1: P1.36 R34.1 R36.2 U1.26 | length 2860.1
  Top Layer w10: U1.26@3447.59,1797.32 3499.31,1745.61 3669.23,1745.61 3669.29,1745.67 3794.43,1745.67 3906.37,1857.61 3906.37,2152.61 3955.37,2201.61 4397.37,2201.61 P1.36@4454.37,2144.61
  Top Layer w30: R36.2@5541.37,1542.74 v4(5541.37,1609.74) ; v4@5543.37,1609.74 R34.1@5543.37,1680.74
  Bottom Layer w30: P1.36@4454.37,2144.61 4526.5,2144.61 4742.37,1928.74 4853.37,1928.74 5172.37,1609.74 v4(5541.37,1609.74)
NO_2: P1.33 R35.1 R37.2 U1.27 | length 3080.4
  Top Layer w10: U1.27@3461.51,1811.24 3509.15,1763.61 3661.78,1763.61 3661.84,1763.67 3786.35,1763.67 3887.37,1864.69 3887.37,2169.61 3962.37,2244.61 P1.33@4354.37,2244.61
  Top Layer w30: R37.2@5743.37,1540.74 v4(5743.37,1608.74) R35.1@5743.37,1680.74
  Bottom Layer w10: P1.33@4354.37,2244.61 P1.33@4379.37,2244.61
  Bottom Layer w20: P1.33@4379.37,2244.61 4427.37,2196.61 4563.37,2196.61
  Bottom Layer w30: 4563.37,2190.74 4767.37,1986.74 4891.37,1986.74 5187.37,1690.74 5661.37,1690.74 v4(5743.37,1608.74)
PA0: KEY_UP.2 P1.32 U1.34 | length 4834.3
  Top Layer w10: KEY_UP.2@2686.46,385.61 KEY_UP.2@2704.46,403.61 ; KEY_UP.2@2689.46,403.61 KEY_UP.2@2704.46,403.61 ; KEY_UP.2@2945.37,403.61 KEY_UP.2@2704.46,403.61 ; U1.34@3558.94,1908.68 3591.02,1876.61 3645.37,1876.61 3833.37,2064.61 3833.37,2210.61 4009.9,2387.13 4411.84,2387.13 P1.32@4454.37,2344.61 ; v1(4080.37,505.61) 2806.46,505.61 KEY_UP.2@2704.46,403.61
  Bottom Layer w10: v1(4080.37,505.61) 4085.37,505.61 4144.37,564.61 v1@4144.37,2387.61
  other v1: 4144.37,2385.61
PA1: P1.29 U1.35 | length 1114.1
  Top Layer w10: U1.35@3572.86,1922.6 3600.86,1894.61 3633.37,1894.61 3815.37,2076.61 3815.37,2235.61 4024.37,2444.61 P1.29@4354.37,2444.61
PA2: P1.30 U1.36 U8.3 | length 6479.6
  Top Layer w10: U1.36@3586.78,1936.52 3605.69,1917.61 3626.37,1917.61 3796.37,2087.61 3796.37,2252.61 4038.37,2494.61 4404.37,2494.61 P1.30@4454.37,2444.61
  Top Layer w30: v4(6782.37,2442.74) v4(7003.37,2221.74)
  Bottom Layer w30: P1.30@4454.37,2444.61 4456.24,2442.74 v4(6782.37,2442.74) ; v4(7003.37,2221.74) 8085.37,2221.74 8849.37,1457.74 U8.3@8849.37,1013.74
PA3: P1.27 U1.37 U8.4 | length 6354
  Top Layer w10: U1.37@3587.02,2075.44 3609.18,2097.61 3722.37,2097.61 3778.37,2153.61 3778.37,2281.61 4041.37,2544.61 P1.27@4354.37,2544.61
  Top Layer w30: v4(6871.37,2493.74) 7147.37,2217.74 v4(7147.37,2152.74)
  Bottom Layer w20: P1.27@4354.37,2544.61 4381.37,2544.61 4432.24,2493.74 4540.37,2493.74
  Bottom Layer w30: 4540.37,2493.74 v4(6871.37,2493.74) ; v4(7147.37,2152.74) 8037.37,2152.74 8749.37,1440.74 U8.4@8749.37,1013.74
PA4: P1.28 Q3.1 U1.40 | length 7466.4
  Top Layer w10: U1.40@3545.02,2117.47 4019.16,2591.61 4407.37,2591.61 P1.28@4454.37,2544.61
  Top Layer w30: v4(6992.37,2544.61) 6992.37,2713.06 7808.91,3529.61 v5(8192.91,3529.61) ; Q3.1@9982.77,3619.87 v5@10105.65,3619.87
  Bottom Layer w30: P1.28@4454.37,2544.61 v4(6992.37,2544.61) ; v5(8192.91,3529.61) 10054.91,3529.61 10105.91,3580.61 v5(10105.91,3619.61)
PA5: P1.25 U1.41 | length 1035.8
  Top Layer w10: U1.41@3531.11,2131.39 4044.32,2644.61 P1.25@4354.37,2644.61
